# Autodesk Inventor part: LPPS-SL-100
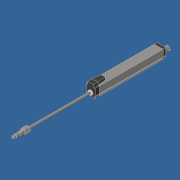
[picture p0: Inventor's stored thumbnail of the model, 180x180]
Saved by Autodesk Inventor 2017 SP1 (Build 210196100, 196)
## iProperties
Created: 2016-12
Part Number: LPPS-SL-100
Material: Stainless Steel
Document SubType Name: Modeling
Designer: JN
Density: 8 g/cm^3
Appearance: Stainless - Brushed
Author: JN
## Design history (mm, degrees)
sketch "Sketch1"
  geometry: C1 r 2.54 at (0, 0)
  constraints: 1 centre point, 1 other
  dimensions: "d0" = 5.08 diameter of C1
extrude "Extrusion1" new body sketch "Sketch1" distance "d1" = 4.572; taper "d2" = 0 deg
sketch "Sketch2"
  geometry: C1 r 3.48 at (0, 0)
  constraints: 1 centre point
  dimensions: "d3" = 6.9596 diameter of C1
extrude "Extrusion2" join sketch "Sketch2" distance "d4" = 8.2042; taper "d5" = 0 deg
workaxis "Work Axis1"
revolve "Revolution2" stored, may be unused: angle "d8" = 90 deg
sketch "Sketch7"
  geometry: L1 (-5.778, 0)-(-2.889, 5.004); L2 (-2.889, 5.004)-(2.889, 5.004); L3 (2.889, 5.004)-(5.778, 0); L4 (5.778, 0)-(2.889, -5.004); L5 (2.889, -5.004)-(-2.889, -5.004); L6 (-2.889, -5.004)-(-5.778, 0); L7 (0, 0)-(0, 8.469); L8 (-0.303, -0.272)-(8.166, -0.272); L9 (0, -3.48)-(0, 0)
  constraints: 18 end point, 3 perpendicular, 1 horizontal, 1 vertical alignment, 14 other
  dimensions: "d20" = 90 deg angle of L8 L7; "d23" = 10.0076 distance between parallel lines of L5 L2
extrude "Extrusion4" join sketch "Sketch7" distance "d21" = 18.03974; taper "d22" = 0 deg
sketch "Sketch8"
  geometry: L1 (3.48, -4.572)-(3.48, -12.776) reference; L2 (0, 1.416)-(0, -21.685); L3 (0, -12.776)-(0, -30.816) reference; L4 (0, 9.356)-(0, -46.226) reference; L5 (5.004, -30.816)-(-5.004, -30.816); L6 (5.004, -30.816)-(0, -30.816) reference; L7 (0, -30.816)-(-5.004, -30.816) reference; L8 (-5.004, -12.776)-(-5.004, -30.816) reference; L9 (-5.004, -30.816)-(-5.004, -12.776); L10 (4.859, -30.943)-(-0.272, -30.943); L11 (-3.48, -12.776)-(3.48, -12.776) reference; L12 (3.48, -4.572)-(3.48, -12.776) reference; L13 (3.48, -12.776)-(3.481, -12.776); L14 (3.481, -12.776)-(9.456, -38.286); L15 (3.481, -12.776)-(9.456, -12.776); L16 (9.456, -38.286)-(9.456, -12.776); A1 r 1.416 centre (0, 0) between (1.416, 0) and (-1.416, 0) reference; 1 further point
  constraints: 16 end point, 2 collinear, 1 horizontal, 1 perpendicular, 1 point on circle, 1 point on line, 1 vertical
revolve "Revolution9" sketch "Sketch8" stored, may be unused: angle "d35" = 90 deg
sketch "Sketch9"
  geometry: C1 r 2.54 at (0, 0)
  constraints: 1 centre point
  dimensions: "d36" = 5.08 diameter of C1
extrude "Extrusion5" join sketch "Sketch9" distance "d37" = 128.524 (= Stroke); taper "d38" = 0 deg
sketch "Sketch10"
  geometry: C1 r 2.54 at (0, 0) reference; C2 r 4.521 at (0, 0)
  constraints: 1 centre point, 1 coincident
  dimensions: "d39" = 9.0424 diameter of C2
extrude "Extrusion6" join sketch "Sketch10" distance "d40" = 2; taper "d41" = 0 deg
sketch "Sketch11"
  geometry: L1 (-9.143, 16.927)-(9.145, 16.927); L2 (9.145, -6.949)-(-9.143, -6.949); L3 (-9.143, -6.949)-(-9.143, 16.927); L4 (-5.778, 0)-(-2.889, -5.004) reference; L5 (5.778, 0)-(2.889, 5.004) reference; L6 (-5.778, 0)-(5.778, 0); L7 (2.889, 5.004)-(-2.889, 5.004) reference; L8 (0, 5.004)-(0, -5.004); L9 (-2.889, -5.004)-(2.889, -5.004) reference; L10 (9.145, -6.949)-(9.145, -4.663); L11 (9.145, -4.663)-(7.621, -4.663); L12 (7.621, -4.663)-(7.621, -2.377); L13 (7.621, -2.377)-(9.145, -2.377); L14 (9.145, 16.927)-(9.145, -2.377); L15 (9.145, -4.663)-(9.145, -6.949); L16 (-9.143, -2.377)-(-7.619, -2.377); L17 (-7.619, -2.377)-(-7.619, -4.663); L18 (-7.619, -4.663)-(-9.143, -4.663)
  constraints: 28 end point, 9 perpendicular, 4 parallel, 4 point on line, 2 horizontal, 2 midpoint
  dimensions: "d42" = 18.288 distance of L1.start L1.end; "d43" = 3.3655 distance from line of L3 L4.start; "d47" = 23.876 distance of L1.end L2.start; "d49" = 1.94564 distance between parallel lines of L2 L9; "d98" = 2.286 distance of L2.start L10.end; "d99" = 1.524 distance of L10.end L11.end; "d100" = 2.286 distance of L11.end L12.end; "d101" = 1.524 distance of L16.start L16.end
extrude "Extrusion7" join sketch "Sketch11" distance "d50" = 9; taper "d51" = 0 deg
sketch "Sketch12"
  geometry: L1 (-9.145, -6.949)-(-9.145, 16.927) reference; L2 (9.143, 16.927)-(9.143, -6.949) reference; L3 (9.143, -6.949)-(-9.145, -6.949) reference; L4 (-9.145, -6.949)-(9.143, -6.949); L5 (-9.145, 16.927)-(9.143, 16.927); L6 (-9.145, 16.927)-(-9.145, -6.949); L7 (-9.145, 16.927)-(9.143, 16.927) reference; L8 (-6.319, 16.927)-(-6.319, 11.593); L9 (6.318, 16.927)-(6.318, 11.593); L10 (-9.145, 11.593)-(-6.319, 11.593); L11 (6.318, 11.593)-(9.143, 11.593)
  constraints: 15 end point, 4 parallel, 2 perpendicular, 2 point on line, 1 collinear
  dimensions: "d52" = 23.876 distance between parallel lines of L4 L5; "d55" = 2.82575 distance between parallel lines of L8 L1; "d56" = 2.82575 distance between parallel lines of L9 L2; "d57" = 18.542 distance between parallel lines of L3 L10; "d58" = 18.542 distance between parallel lines of L3 L11
extrude "Extrusion8" cut sketch "Sketch12" distance "d59" = 9; taper "d60" = 0 deg
mirror "Mirror1"
sketch "Sketch13"
  geometry: L1 (9.145, 11.593)-(6.319, 11.593) reference; L2 (-6.319, 16.927)-(6.319, 16.927); L3 (6.319, 16.927)-(6.319, 11.593); L4 (6.319, 11.593)-(-6.319, 11.593); L5 (-6.319, 11.593)-(-6.319, 16.927)
  constraints: 8 end point, 2 parallel, 1 horizontal, 1 perpendicular
workplane "Work Plane1"
sketch "Sketch14"
  geometry: L1 (6.319, 16.927)-(-6.319, 16.927) reference; L2 (-4.109, 16.927)-(4.121, 16.927); L3 (4.121, 16.927)-(4.121, 11.558); L4 (4.121, 11.558)-(-4.109, 11.558); L5 (-4.109, 11.558)-(-4.109, 16.927); L6 (-6.319, 16.927)-(-6.319, 11.593) reference; L7 (6.319, 11.593)-(6.319, 16.927) reference; 1 further point
  constraints: 8 end point, 2 parallel, 2 perpendicular, 1 horizontal, 1 point on line
  dimensions: "d62" = 8.2296 distance of L3.end L4.end; "d63" = 2.2098 distance between parallel lines of L6 L5; "d65" = 2.6844 distance from line of point (0.006, 14.242) L1; "d66" = 4.1148 distance from line of L5 point (0.006, 14.242)
sketch "3D Sketch1"
loft "Loft1" sketch "3D Sketch1" dims "d67" = 0, "d68" = 90 deg, "d69" = 0, "d70" = 90 deg, "d71" = 0, "d72" = 90 deg
sketch "Sketch15"
  geometry: L1 (-6.319, 11.593)-(-9.143, 11.593) reference; L2 (9.145, -6.949)-(9.145, 11.593) reference; L3 (-9.143, 11.593)-(9.145, 11.593); L4 (9.145, -6.949)-(-9.143, -6.949); L5 (7.621, -2.377)-(9.145, -2.377) reference; L6 (9.145, -2.377)-(7.621, -2.377); L7 (7.621, -4.663)-(7.621, -2.377) reference; L8 (7.621, -2.377)-(7.621, -4.663); L9 (9.145, -4.663)-(7.621, -4.663) reference; L10 (7.621, -4.663)-(9.145, -4.663); L11 (-9.143, -2.377)-(-7.619, -2.377) reference; L12 (-7.619, -4.663)-(-9.143, -4.663) reference; L13 (-9.143, -4.663)-(-7.619, -4.663); L14 (-7.619, -2.377)-(-7.619, -4.663) reference; L15 (-7.619, -4.663)-(-7.619, -2.377); L16 (-9.143, 11.593)-(-9.143, -2.377) reference; L17 (-7.619, -2.377)-(-9.143, -2.377); L18 (9.145, 11.593)-(9.145, -2.377); L19 (9.145, -4.663)-(9.145, -6.949); L20 (-9.143, -6.949)-(-9.143, -4.663); L21 (-9.143, -2.377)-(-9.143, 11.593)
  constraints: 24 end point, 5 parallel, 5 perpendicular, 3 collinear, 1 horizontal
extrude "Extrusion9" new body sketch "Sketch15" distance "d73" = 131.5466 (= Body); taper "d74" = 0 deg
sketch "Sketch16"
  geometry: L1 (-9.143, 11.593)-(-9.143, -6.949) reference; L2 (-9.143, -6.949)-(9.145, -6.949) reference; L3 (-9.143, 11.593)-(9.145, 11.593); L4 (9.145, -6.949)-(-9.143, -6.949); L5 (7.621, -2.377)-(9.145, -2.377) reference; L6 (9.145, -2.377)-(7.621, -2.377); L7 (9.145, -4.663)-(7.621, -4.663) reference; L8 (7.621, -2.377)-(7.621, -4.663); L9 (7.621, -4.663)-(9.145, -4.663); L10 (-9.143, -2.377)-(-7.619, -2.377) reference; L11 (-9.143, -2.377)-(-7.619, -2.377); L12 (-7.619, -2.377)-(-7.619, -4.663) reference; L13 (-7.619, -2.377)-(-7.619, -4.663); L14 (-7.619, -4.663)-(-9.143, -4.663) reference; L15 (-7.619, -4.663)-(-9.143, -4.663); L16 (-9.143, -6.949)-(-9.143, -4.663); L17 (-9.143, -2.377)-(-9.143, 11.593); L18 (9.145, 11.593)-(9.145, -2.377); L19 (9.145, -4.663)-(9.145, -6.949)
  constraints: 24 end point, 5 parallel, 4 perpendicular, 3 collinear, 2 horizontal
extrude "Extrusion10" new body sketch "Sketch16" distance "d75" = 6.0071; taper "d76" = 0 deg
sketch "Sketch17"
  geometry: L1 (-9.143, 11.593)-(9.145, 11.593) reference; L2 (9.145, 11.593)-(9.145, -2.377) reference; L3 (9.145, -6.949)-(-9.143, -6.949) reference; L4 (-9.143, -6.949)-(-9.143, -4.663) reference; L5 (-9.143, -4.663)-(-7.619, -4.663) reference; L6 (-7.619, -4.663)-(-7.619, -2.377) reference; L7 (-7.619, -2.377)-(-9.143, -2.377) reference; L8 (-9.143, -2.377)-(-9.143, 11.593) reference; L9 (9.145, -2.377)-(7.621, -2.377) reference; L10 (7.621, -2.377)-(7.621, -4.663) reference; L11 (7.621, -4.663)-(9.145, -4.663) reference; L12 (9.145, -4.663)-(9.145, -6.949) reference; C1 r 2.54 at (0, 0) reference; C2 r 1.416 at (0, 0) reference; C3 r 4.051 at (0, 0)
  constraints: 1 centre point, 1 coincident
  dimensions: "d77" = 8.1026 diameter of C3
extrude "Extrusion11" new body sketch "Sketch17" distance "d78" = 5; taper "d79" = 0 deg
sketch "Sketch18"
  geometry: C1 r 1.416 at (0, 0) reference; C2 r 5 at (0, 0)
  constraints: 1 centre point, 1 coincident
  dimensions: "d80" = 10 diameter of C2
extrude "Extrusion12" new body sketch "Sketch18" distance "d81" = 8; taper "d82" = 0 deg
shell "Shell2" dims "d84" = 1.397
workaxis "Work Axis4"
workplane "Work Plane2"
sketch "Sketch19"
  geometry: L1 (-5, -8)-(5, -8) reference; L2 (0, -8)-(0, -6.095); 1 further point
  constraints: 2 end point, 1 coincident, 1 midpoint, 1 vertical
  dimensions: "d85" = 1.905 distance of L2.start L2.end
hole "Hole1" sketch "Sketch19" at (0, -6.095) diameter "d86" = 2.3876; stored, may be unused: countersink angle "d90" = 82 deg, drill point angle "d92" = 118 deg; dims "d87" = 19.05, "d88" = 9.525, "d89" = 6.35, "d91" = 25.4
body "Solid1"
sketch "Sketch3"
  geometry: L1 (-2.54, 0)-(2.54, 0) reference; L2 (1.416, 0)-(0, 0); L3 (0, 0)-(0, 1.416); A1 r 1.416 centre (0, 0) between (1.416, 0) and (0, 1.416)
  constraints: 4 end point, 2 point on circle, 1 centre point, 1 midpoint, 1 vertical
  dimensions: "d6" = 2.8321 diameter of A1
body "Solid2"
body "Solid3"
body "Solid4"
body "Solid5"
node "Project Cut Edges1"
other parameters: "Stroke" = 128.524 [user parameter; used in 1 equation term], "Body" = 131.5466 [user parameter; used in 1 equation term], "d53" = 5.334, "d61" = 16.51
